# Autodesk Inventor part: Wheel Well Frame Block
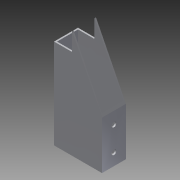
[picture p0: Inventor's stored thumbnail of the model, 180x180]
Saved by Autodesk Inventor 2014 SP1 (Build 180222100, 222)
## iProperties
Created: 2014-06
Part Number: Wheel Well Frame Block
Material: Aluminum 6061
Document SubType Name: Modeling
Designer: Michael
Density: 2.71 g/cm^3
Appearance: Aluminum - Flat
Author: Michael
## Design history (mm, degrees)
sketch "Sketch1"
  geometry: L1 (-25.4, -57.15)-(25.4, -57.15); L2 (25.4, -57.15)-(25.4, 57.15); L3 (25.4, 57.15)-(-25.4, 57.15); L4 (-25.4, 57.15)-(-25.4, -57.15); L5 (-25.4, -57.15)-(25.4, 57.15); L6 (25.4, -57.15)-(-25.4, 57.15); 1 further point
  constraints: 12 end point, 2 midpoint, 2 parallel, 1 horizontal, 1 perpendicular
  dimensions: "d0" = 50.8 distance between parallel lines of L2 L4; "d1" = 114.3 distance between parallel lines of L3 L1
extrude "Extrusion1" new body sketch "Sketch1" distance "d2" = 25.4; taper "d3" = 0 deg
sketch "Sketch2"
  geometry: L1 (0, 0)-(50.8, 0) reference; L2 (50.8, 0)-(50.8, 25.4) reference; L3 (0, 25.4)-(50.8, 25.4) reference; L4 (0, 0)-(0, 25.4) reference; L5 (49.213, 23.812)-(49.213, 1.588); L6 (49.213, 1.588)-(1.587, 1.588); L7 (1.587, 1.588)-(1.588, 23.813); L8 (1.588, 23.813)-(49.213, 23.812); 1 further point
  constraints: 8 end point, 3 other
  dimensions: "d4" = 1.5875 distance between parallel lines of L4 L7
extrude "Extrusion2" cut sketch "Sketch2" stored distance "d5" = 25.4; taper "d6" = 0 deg
sketch "Sketch3"
  geometry: L1 (-25.4, 57.15)-(-6.35, 57.15); L2 (-6.35, 57.15)-(-6.35, 38.1); L3 (-6.35, 38.1)-(-25.4, 38.1); L4 (-25.4, 38.1)-(-25.4, 57.15); 1 further point
  constraints: 8 end point, 2 parallel, 1 horizontal, 1 perpendicular
  dimensions: "d7" = 19.05 distance of L2.end L3.end; "d8" = 19.05 distance between parallel lines of L1 L3 (= d7)
extrude "Extrusion3" cut sketch "Sketch3" stored distance "d9" = 25.4; taper "d10" = 0 deg
sketch "Sketch4"
  geometry: L1 (25.4, -57.15)-(25.4, 57.15) reference; L2 (25.4, 57.15)-(-6.35, 57.15) reference; L3 (-6.35, 57.15)-(25.4, -6.35); 1 further point
  constraints: 2 end point, 1 point on line
  dimensions: "d11" = 50.8 distance of L1.start L3.end
extrude "Extrusion4" cut sketch "Sketch4" stored distance "d12" = 25.4; taper "d13" = 0 deg
sketch "Sketch5"
  geometry: L1 (25.4, 50.8)-(0, 50.8) reference; L2 (25.4, 0)-(0, 0) reference; C1 r 2.489 at (12.7, 12.7); C2 r 2.489 at (12.7, 38.1); 3 further points
  constraints: 2 centre point, 2 midpoint, 2 vertical alignment
  dimensions: "d14" = 4.9784 diameter of C1; "d15" = 12.7 distance from line of L2 C1.centre; "d16" = 4.9784 diameter of C2 (= d14); "d17" = 12.7 distance from line of L1 C2.centre (= d15)
extrude "Extrusion5" cut sketch "Sketch5" stored distance "d18" = 0; taper "d19" = 0 deg
body "Solid1"
